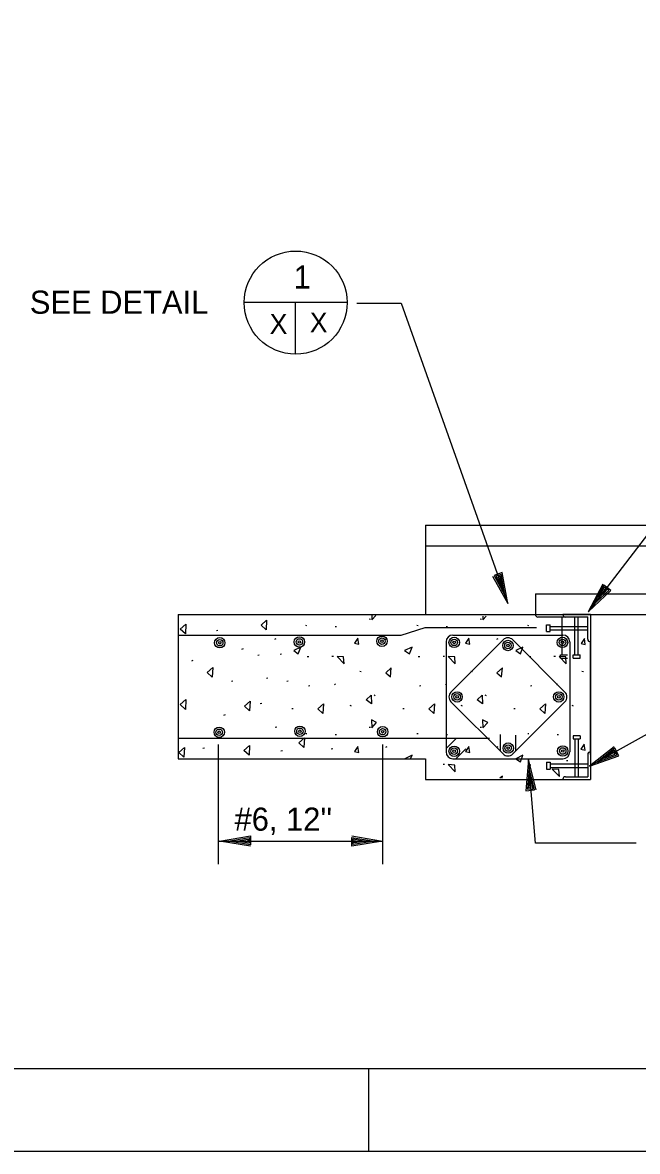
# Model space of a CAD drawing. Extents: x -11983 to -11903, y -13969.5 to -13913.5.
# Drawn here: x -11969.21 to -11961.75, y -13969.48 to -13955.79 of the extents above; entities that cross this region are included whole.
import ezdxf

# ---------------------------------------------------------------- set-up
doc = ezdxf.new("R2010")
doc.units = 0
for name, color, linetype in [('Level 1', 7, 'Continuous'), ('Level 2', 7, 'Continuous'), ('Level 22', 7, 'Continuous'), ('Level 25', 7, 'Continuous'), ('Level 3', 7, 'Continuous'), ('Level 44', 7, 'Continuous'), ('Level 50', 7, 'Continuous'), ('Level 6', 7, 'Continuous')]:
    doc.layers.add(name, color=color, linetype=linetype)

msp = doc.modelspace()

# ---------------------------------------------------------------- linework, layer by layer
at = {"layer": 'Level 1'}
msp.add_line((-11965.012, -13968.481), (-11965.012, -13969.481), dxfattribs=at)
for points in [[(-11983.012, -13913.481), (-11903.012, -13913.481), (-11903.012, -13969.481), (-11983.012, -13969.481)], [(-11980.012, -13914.481), (-11904.012, -13914.481), (-11904.012, -13968.481), (-11980.012, -13968.481)]]:
    msp.add_lwpolyline(points, close=True, dxfattribs=at)
at = {"layer": 'Level 2'}
for p, q in [((-11964.319, -13961.887), (-11944.556, -13961.887)), ((-11964.319, -13961.887), (-11964.319, -13962.97)), ((-11964.319, -13962.137), (-11944.556, -13962.137)), ((-11962.988, -13962.72), (-11944.556, -13962.72)), ((-11962.988, -13962.72), (-11962.988, -13962.97)), ((-11967.321, -13962.97), (-11962.654, -13962.97)), ((-11967.321, -13962.97), (-11967.321, -13964.72)), ((-11962.988, -13962.97), (-11962.321, -13962.97)), ((-11962.654, -13962.97), (-11962.654, -13962.97)), ((-11962.654, -13962.97), (-11962.654, -13962.97)), ((-11962.321, -13962.97), (-11962.654, -13962.97)), ((-11962.321, -13962.97), (-11962.321, -13963.303)), ((-11962.321, -13962.97), (-11938.321, -13962.97)), ((-11962.321, -13962.97), (-11962.321, -13963.303)), ((-11964.326, -13963.128), (-11962.974, -13963.128)), ((-11962.957, -13963.001), (-11962.352, -13963.001)), ((-11962.852, -13963.178), (-11962.852, -13963.095)), ((-11962.852, -13963.095), (-11962.81, -13963.095)), ((-11962.852, -13963.178), (-11962.852, -13963.095)), ((-11962.852, -13963.095), (-11962.81, -13963.095)), ((-11962.81, -13963.178), (-11962.81, -13963.095)), ((-11962.81, -13963.178), (-11962.81, -13963.095)), ((-11962.81, -13963.115), (-11962.662, -13963.115)), ((-11962.81, -13963.115), (-11962.352, -13963.115)), ((-11962.662, -13963.459), (-11962.662, -13963.001)), ((-11962.623, -13963.001), (-11962.352, -13963.001)), ((-11962.621, -13963.115), (-11962.352, -13963.115)), ((-11962.508, -13963.459), (-11962.508, -13963.001)), ((-11962.467, -13963.459), (-11962.467, -13963.001)), ((-11962.352, -13963.271), (-11962.352, -13963.001)), ((-11962.352, -13963.271), (-11962.352, -13963.001)), ((-11967.321, -13963.22), (-11964.614, -13963.22)), ((-11963.988, -13963.22), (-11962.654, -13963.22)), ((-11962.852, -13963.178), (-11962.81, -13963.178)), ((-11962.852, -13963.178), (-11962.81, -13963.178)), ((-11962.81, -13963.157), (-11962.662, -13963.157)), ((-11962.81, -13963.157), (-11962.352, -13963.157)), ((-11962.621, -13963.157), (-11962.352, -13963.157)), ((-11964.071, -13963.303), (-11964.071, -13964.636)), ((-11962.571, -13963.303), (-11962.571, -13964.636)), ((-11962.321, -13963.303), (-11962.321, -13963.303)), ((-11962.321, -13963.303), (-11962.321, -13963.303)), ((-11962.321, -13963.303), (-11962.321, -13964.637)), ((-11962.683, -13963.459), (-11962.6, -13963.459)), ((-11962.683, -13963.499), (-11962.683, -13963.459)), ((-11962.683, -13963.5), (-11962.6, -13963.5)), ((-11962.529, -13963.459), (-11962.446, -13963.459)), ((-11962.529, -13963.499), (-11962.529, -13963.459)), ((-11962.529, -13963.5), (-11962.446, -13963.5)), ((-11962.446, -13963.499), (-11962.446, -13963.459)), ((-11967.321, -13964.47), (-11963.544, -13964.47)), ((-11962.529, -13964.439), (-11962.446, -13964.439)), ((-11962.529, -13964.439), (-11962.446, -13964.439)), ((-11962.529, -13964.441), (-11962.529, -13964.48)), ((-11962.529, -13964.441), (-11962.529, -13964.48)), ((-11962.529, -13964.48), (-11962.446, -13964.48)), ((-11962.529, -13964.48), (-11962.446, -13964.48)), ((-11962.508, -13964.48), (-11962.508, -13964.938)), ((-11962.508, -13964.48), (-11962.508, -13964.938)), ((-11962.467, -13964.48), (-11962.467, -13964.938)), ((-11962.467, -13964.48), (-11962.467, -13964.938)), ((-11962.446, -13964.441), (-11962.446, -13964.48)), ((-11962.446, -13964.441), (-11962.446, -13964.48)), ((-11966.834, -13964.547), (-11966.834, -13965.997)), ((-11964.84, -13964.547), (-11964.84, -13965.997)), ((-11962.321, -13964.637), (-11962.321, -13964.637)), ((-11962.321, -13964.637), (-11962.321, -13964.97)), ((-11962.321, -13964.637), (-11962.321, -13964.637)), ((-11962.321, -13964.637), (-11962.321, -13964.97)), ((-11967.321, -13964.72), (-11964.321, -13964.72)), ((-11964.321, -13964.72), (-11964.321, -13964.97)), ((-11963.988, -13964.72), (-11962.654, -13964.72)), ((-11962.852, -13964.762), (-11962.852, -13964.845)), ((-11962.852, -13964.762), (-11962.81, -13964.762)), ((-11962.852, -13964.762), (-11962.852, -13964.845)), ((-11962.852, -13964.762), (-11962.81, -13964.762)), ((-11962.81, -13964.762), (-11962.81, -13964.845)), ((-11962.81, -13964.762), (-11962.81, -13964.845)), ((-11962.352, -13964.668), (-11962.352, -13964.938)), ((-11962.352, -13964.668), (-11962.352, -13964.938)), ((-11962.852, -13964.845), (-11962.81, -13964.845)), ((-11962.852, -13964.845), (-11962.81, -13964.845)), ((-11962.81, -13964.782), (-11962.352, -13964.782)), ((-11962.81, -13964.782), (-11962.352, -13964.782)), ((-11962.81, -13964.824), (-11962.352, -13964.824)), ((-11962.81, -13964.824), (-11962.352, -13964.824)), ((-11964.321, -13964.97), (-11962.654, -13964.97)), ((-11964.321, -13964.97), (-11962.654, -13964.97)), ((-11962.654, -13964.97), (-11962.654, -13964.97)), ((-11962.654, -13964.97), (-11962.654, -13964.97)), ((-11962.623, -13964.938), (-11962.352, -13964.938)), ((-11962.623, -13964.938), (-11962.352, -13964.938)), ((-11966.834, -13965.718), (-11964.84, -13965.718))]:
    msp.add_line(p, q, dxfattribs=at)
for centre, start, end in [((-11962.957, -13962.97), 180, 270), ((-11962.623, -13962.97), 180, 270), ((-11962.321, -13963.271), 180, 270), ((-11962.321, -13963.271), 180, 270), ((-11962.321, -13964.668), 90, 180), ((-11962.321, -13964.668), 90, 180), ((-11962.623, -13964.969), 90, 180), ((-11962.623, -13964.969), 90, 180)]:
    msp.add_arc(centre, 0.0312, start, end, dxfattribs=at)
at = {"layer": 'Level 22'}
for p, q in [((-11964.614, -13963.22), (-11964.326, -13963.128)), ((-11964.012, -13963.911), (-11963.38, -13963.278)), ((-11963.262, -13963.278), (-11962.63, -13963.911)), ((-11962.321, -13964.668), (-11962.321, -13963.303)), ((-11963.38, -13964.661), (-11964.012, -13964.028)), ((-11962.63, -13964.028), (-11963.262, -13964.661)), ((-11964.07, -13964.597), (-11963.952, -13964.479)), ((-11963.411, -13964.626), (-11963.411, -13964.427)), ((-11963.226, -13964.626), (-11963.226, -13964.433)), ((-11963.948, -13964.718), (-11963.83, -13964.6))]:
    msp.add_line(p, q, dxfattribs=at)
for centre, start, end in [((-11963.988, -13963.303), 90, 180), ((-11963.321, -13963.337), 44.9969, 135), ((-11962.654, -13963.303), 0, 90), ((-11963.953, -13963.97), 135, 224.9976), ((-11962.689, -13963.97), 315, 45), ((-11963.988, -13964.636), 180, 270), ((-11962.654, -13964.636), 270, 0), ((-11963.321, -13964.602), 225.0028, 315)]:
    msp.add_arc(centre, 0.0833, start, end, dxfattribs=at)
at = {"layer": 'Level 25'}
msp.add_line((-11962.654, -13964.97), (-11962.321, -13964.97), dxfattribs=at)
msp.add_line((-11962.654, -13964.97), (-11962.321, -13964.97), dxfattribs=at)
at = {"layer": 'Level 3'}
for p, q in [((-11965.27, -13959.189), (-11966.52, -13959.189)), ((-11965.895, -13959.814), (-11965.895, -13959.189)), ((-11963.357, -13962.738), (-11963.357, -13962.738)), ((-11963.322, -13962.836), (-11963.322, -13962.836)), ((-11962.286, -13962.855), (-11962.286, -13962.855)), ((-11962.349, -13962.938), (-11962.349, -13962.938)), ((-11963.073, -13964.729), (-11963.073, -13964.729)), ((-11962.24, -13964.761), (-11962.24, -13964.761)), ((-11963.064, -13964.833), (-11963.064, -13964.833)), ((-11962.331, -13964.811), (-11962.331, -13964.811))]:
    msp.add_line(p, q, dxfattribs=at)
for points in [[(-11965.154, -13959.197), (-11964.617, -13959.197), (-11963.322, -13962.836)], [(-11960.827, -13961.393), (-11961.163, -13961.393), (-11962.349, -13962.938)], [(-11963.506, -13962.505), (-11963.322, -13962.836), (-11963.389, -13962.463), (-11963.489, -13962.499), (-11963.357, -13962.738), (-11963.403, -13962.485), (-11963.467, -13962.508), (-11963.391, -13962.644), (-11963.416, -13962.507), (-11963.442, -13962.516), (-11963.425, -13962.546)], [(-11962.17, -13962.604), (-11962.349, -13962.938), (-11962.072, -13962.679), (-11962.156, -13962.615), (-11962.286, -13962.855), (-11962.098, -13962.68), (-11962.152, -13962.638), (-11962.225, -13962.776), (-11962.123, -13962.68), (-11962.145, -13962.663), (-11962.161, -13962.694)], [(-11960.809, -13964.157), (-11961.149, -13964.157), (-11962.331, -13964.811)], [(-11962.034, -13964.576), (-11962.331, -13964.811), (-11961.974, -13964.684), (-11962.025, -13964.591), (-11962.24, -13964.761), (-11961.997, -13964.674), (-11962.03, -13964.615), (-11962.153, -13964.712), (-11962.021, -13964.665), (-11962.035, -13964.64), (-11962.062, -13964.662)], [(-11962.979, -13965.096), (-11963.073, -13964.729), (-11963.102, -13965.107), (-11962.997, -13965.098), (-11963.064, -13964.833), (-11963.084, -13965.09), (-11963.016, -13965.084), (-11963.055, -13964.932), (-11963.065, -13965.072), (-11963.037, -13965.069), (-11963.046, -13965.036)], [(-11961.767, -13965.744), (-11962.985, -13965.744), (-11963.073, -13964.729)]]:
    msp.add_lwpolyline(points, dxfattribs=at)
msp.add_circle((-11965.895, -13959.189), 0.625, dxfattribs=at)
at = {"layer": 'Level 44'}
for p, q in [((-11965.758, -13963.108), (-11965.771, -13963.105)), ((-11965.399, -13963.119), (-11965.417, -13963.119)), ((-11964.989, -13963.03), (-11965.002, -13963.029)), ((-11964.411, -13963.108), (-11964.425, -13963.105)), ((-11964.053, -13963.119), (-11964.071, -13963.119)), ((-11963.642, -13963.03), (-11963.656, -13963.029)), ((-11963.065, -13963.108), (-11963.078, -13963.105)), ((-11962.706, -13963.119), (-11962.724, -13963.119)), ((-11966.839, -13963.164), (-11966.857, -13963.169)), ((-11966.135, -13963.265), (-11966.151, -13963.273)), ((-11964.789, -13963.265), (-11964.805, -13963.273)), ((-11963.442, -13963.265), (-11963.458, -13963.273)), ((-11966.532, -13963.389), (-11966.55, -13963.394)), ((-11967.141, -13963.53), (-11967.159, -13963.535)), ((-11966.337, -13963.463), (-11966.355, -13963.468)), ((-11966.067, -13963.45), (-11966.085, -13963.455)), ((-11965.737, -13963.486), (-11965.755, -13963.486)), ((-11965.438, -13963.48), (-11965.455, -13963.48)), ((-11964.39, -13963.486), (-11964.408, -13963.486)), ((-11964.091, -13963.48), (-11964.108, -13963.48)), ((-11963.043, -13963.486), (-11963.061, -13963.486)), ((-11962.745, -13963.48), (-11962.762, -13963.48)), ((-11962.744, -13963.48), (-11962.761, -13963.48)), ((-11965.099, -13963.666), (-11965.116, -13963.663)), ((-11963.752, -13963.666), (-11963.769, -13963.663)), ((-11962.405, -13963.666), (-11962.423, -13963.663)), ((-11966.657, -13963.78), (-11966.675, -13963.785)), ((-11966.231, -13963.743), (-11966.249, -13963.748)), ((-11965.986, -13963.78), (-11966.004, -13963.785)), ((-11965.412, -13963.817), (-11965.425, -13963.822)), ((-11964.065, -13963.817), (-11964.078, -13963.822)), ((-11962.718, -13963.817), (-11962.731, -13963.822)), ((-11965.722, -13963.835), (-11965.74, -13963.84)), ((-11964.929, -13963.958), (-11964.944, -13963.949)), ((-11964.376, -13963.835), (-11964.394, -13963.84)), ((-11963.582, -13963.958), (-11963.597, -13963.949)), ((-11963.029, -13963.835), (-11963.047, -13963.84)), ((-11966.306, -13964.049), (-11966.324, -13964.054)), ((-11965.219, -13964.082), (-11965.234, -13964.076)), ((-11963.873, -13964.082), (-11963.887, -13964.076)), ((-11962.526, -13964.082), (-11962.54, -13964.076)), ((-11966.751, -13964.189), (-11966.769, -13964.194)), ((-11965.926, -13964.114), (-11965.941, -13964.116)), ((-11964.58, -13964.114), (-11964.594, -13964.116)), ((-11963.233, -13964.114), (-11963.248, -13964.116)), ((-11966.124, -13964.336), (-11966.142, -13964.341)), ((-11964.989, -13964.341), (-11965.002, -13964.34)), ((-11963.642, -13964.341), (-11963.656, -13964.34)), ((-11965.758, -13964.419), (-11965.771, -13964.417)), ((-11965.399, -13964.431), (-11965.417, -13964.431)), ((-11964.411, -13964.419), (-11964.425, -13964.417)), ((-11964.053, -13964.431), (-11964.071, -13964.431)), ((-11963.065, -13964.419), (-11963.078, -13964.417)), ((-11962.706, -13964.431), (-11962.724, -13964.431)), ((-11967.002, -13964.592), (-11967.02, -13964.597)), ((-11966.055, -13964.622), (-11966.073, -13964.627)), ((-11965.446, -13964.598), (-11965.464, -13964.603)), ((-11964.789, -13964.576), (-11964.805, -13964.584)), ((-11963.442, -13964.576), (-11963.458, -13964.584)), ((-11962.595, -13964.744), (-11962.612, -13964.744)), ((-11962.595, -13964.744), (-11962.612, -13964.744)), ((-11964.091, -13964.791), (-11964.108, -13964.791)), ((-11963.043, -13964.798), (-11963.061, -13964.798)), ((-11963.043, -13964.798), (-11963.061, -13964.798))]:
    msp.add_line(p, q, dxfattribs=at)
for points in [[(-11964.973, -13962.981), (-11964.97, -13963.034)], [(-11964.97, -13963.034), (-11964.923, -13962.982)], [(-11963.626, -13962.991), (-11963.623, -13963.034)], [(-11963.623, -13963.034), (-11963.585, -13962.992)], [(-11964.501, -13964.72), (-11964.484, -13964.677), (-11964.571, -13964.72)], [(-11963.388, -13964.93), (-11963.417, -13964.955)], [(-11963.388, -13964.93), (-11963.417, -13964.955)], [(-11963.391, -13964.955), (-11963.388, -13964.93)], [(-11963.391, -13964.955), (-11963.388, -13964.93)]]:
    msp.add_lwpolyline(points, dxfattribs=at)
for points in [[(-11967.232, -13963.205), (-11967.294, -13963.148), (-11967.226, -13963.087)], [(-11966.253, -13963.156), (-11966.315, -13963.099), (-11966.247, -13963.038)], [(-11965.13, -13963.332), (-11965.139, -13963.259), (-11965.18, -13963.32)], [(-11963.783, -13963.332), (-11963.793, -13963.259), (-11963.834, -13963.32)], [(-11962.383, -13963.335), (-11962.393, -13963.262), (-11962.434, -13963.323)], [(-11965.863, -13963.447), (-11965.831, -13963.365), (-11965.919, -13963.408)], [(-11964.516, -13963.447), (-11964.484, -13963.365), (-11964.573, -13963.408)], [(-11963.169, -13963.447), (-11963.138, -13963.365), (-11963.226, -13963.408)], [(-11965.313, -13963.484), (-11965.393, -13963.48), (-11965.306, -13963.568)], [(-11963.966, -13963.484), (-11964.046, -13963.48), (-11963.96, -13963.568)], [(-11962.62, -13963.484), (-11962.7, -13963.48), (-11962.613, -13963.568)], [(-11966.906, -13963.73), (-11966.968, -13963.673), (-11966.899, -13963.612)], [(-11964.735, -13963.618), (-11964.803, -13963.678), (-11964.746, -13963.725)], [(-11963.388, -13963.618), (-11963.456, -13963.678), (-11963.4, -13963.725)], [(-11964.976, -13964.053), (-11965.04, -13964.004), (-11964.979, -13963.95)], [(-11963.63, -13964.053), (-11963.694, -13964.004), (-11963.632, -13963.95)], [(-11967.232, -13964.121), (-11967.294, -13964.064), (-11967.226, -13964.003)], [(-11966.454, -13964.139), (-11966.516, -13964.082), (-11966.448, -13964.021)], [(-11965.566, -13964.173), (-11965.628, -13964.116), (-11965.559, -13964.055)], [(-11964.219, -13964.173), (-11964.281, -13964.116), (-11964.213, -13964.055)], [(-11962.873, -13964.173), (-11962.934, -13964.116), (-11962.866, -13964.055)], [(-11964.97, -13964.346), (-11964.913, -13964.282), (-11964.976, -13964.248)], [(-11963.623, -13964.346), (-11963.566, -13964.282), (-11963.63, -13964.248)], [(-11965.795, -13964.584), (-11965.857, -13964.527), (-11965.789, -13964.466)], [(-11967.251, -13964.7), (-11967.313, -13964.643), (-11967.245, -13964.582)], [(-11966.46, -13964.676), (-11966.522, -13964.619), (-11966.454, -13964.558)], [(-11965.13, -13964.644), (-11965.139, -13964.571), (-11965.18, -13964.632)], [(-11963.783, -13964.644), (-11963.793, -13964.571), (-11963.834, -13964.632)], [(-11962.385, -13964.615), (-11962.395, -13964.542), (-11962.436, -13964.603)], [(-11962.385, -13964.615), (-11962.395, -13964.542), (-11962.436, -13964.603)], [(-11963.169, -13964.759), (-11963.138, -13964.677), (-11963.226, -13964.72)], [(-11963.966, -13964.796), (-11964.046, -13964.791), (-11963.96, -13964.88)], [(-11962.704, -13964.851), (-11962.784, -13964.847), (-11962.697, -13964.935)], [(-11962.704, -13964.851), (-11962.784, -13964.847), (-11962.697, -13964.935)]]:
    msp.add_lwpolyline(points, close=True, dxfattribs=at)
at = {"layer": 'Level 50'}
for p, q in [((-11966.817, -13965.718), (-11966.817, -13965.718)), ((-11966.713, -13965.718), (-11966.713, -13965.718)), ((-11964.944, -13965.718), (-11964.944, -13965.718)), ((-11964.84, -13965.718), (-11964.84, -13965.718))]:
    msp.add_line(p, q, dxfattribs=at)
for points in [[(-11966.443, -13965.78), (-11966.817, -13965.718), (-11966.443, -13965.656), (-11966.443, -13965.762), (-11966.713, -13965.718), (-11966.459, -13965.676), (-11966.459, -13965.744), (-11966.613, -13965.718), (-11966.475, -13965.696), (-11966.475, -13965.724), (-11966.509, -13965.718)], [(-11965.214, -13965.656), (-11964.84, -13965.718), (-11965.214, -13965.78), (-11965.214, -13965.674), (-11964.944, -13965.718), (-11965.198, -13965.76), (-11965.198, -13965.692), (-11965.044, -13965.718), (-11965.182, -13965.74), (-11965.182, -13965.712), (-11965.148, -13965.718)]]:
    msp.add_lwpolyline(points, dxfattribs=at)
at = {"layer": 'Level 6'}
for centre, radius in [((-11966.816, -13963.313), 0.0633), ((-11965.85, -13963.304), 0.0633), ((-11965.85, -13963.304), 0.0396), ((-11964.848, -13963.295), 0.0633), ((-11964.848, -13963.295), 0.0396), ((-11963.972, -13963.309), 0.0633), ((-11963.972, -13963.309), 0.0396), ((-11962.659, -13963.309), 0.0633), ((-11962.659, -13963.309), 0.0396), ((-11966.816, -13963.313), 0.0396), ((-11966.816, -13963.313), 0.0158), ((-11965.85, -13963.304), 0.0158), ((-11964.848, -13963.295), 0.0158), ((-11963.972, -13963.309), 0.0158), ((-11963.32, -13963.347), 0.0633), ((-11963.32, -13963.347), 0.0396), ((-11963.32, -13963.347), 0.0158), ((-11962.659, -13963.309), 0.0158), ((-11963.937, -13963.97), 0.0633), ((-11963.937, -13963.97), 0.0396), ((-11963.937, -13963.97), 0.0158), ((-11962.704, -13963.97), 0.0633), ((-11962.704, -13963.97), 0.0396), ((-11962.704, -13963.97), 0.0158), ((-11966.822, -13964.399), 0.0633), ((-11966.822, -13964.399), 0.0396), ((-11965.843, -13964.387), 0.0633), ((-11965.843, -13964.387), 0.0396), ((-11964.84, -13964.392), 0.0633), ((-11964.84, -13964.392), 0.0396), ((-11966.822, -13964.399), 0.0158), ((-11965.843, -13964.387), 0.0158), ((-11964.84, -13964.392), 0.0158), ((-11963.972, -13964.629), 0.0633), ((-11963.972, -13964.629), 0.0396), ((-11963.972, -13964.629), 0.0158), ((-11963.317, -13964.59), 0.0633), ((-11963.317, -13964.59), 0.0396), ((-11963.317, -13964.59), 0.0158), ((-11962.656, -13964.626), 0.0633), ((-11962.656, -13964.626), 0.0396), ((-11962.656, -13964.626), 0.0158)]:
    msp.add_circle(centre, radius, dxfattribs=at)

# ---------------------------------------------------------------- texts
at = {"layer": 'Level 2'}
for p in [(-11966.21, -13959.568), (-11965.723, -13959.55)]:
    msp.add_text('X', height=0.24, dxfattribs=at).set_placement(p)
at = {"layer": 'Level 22'}
msp.add_text("#6, 12''", height=0.28, dxfattribs=at).set_placement((-11966.636, -13965.592))
at = {"layer": 'Level 3'}
for s, p in [('1', (-11965.92, -13959.019)), ('SEE DETAIL', (-11969.119, -13959.324))]:
    msp.add_text(s, height=0.28, dxfattribs=at).set_placement(p)

doc.saveas('drawing.dxf')
